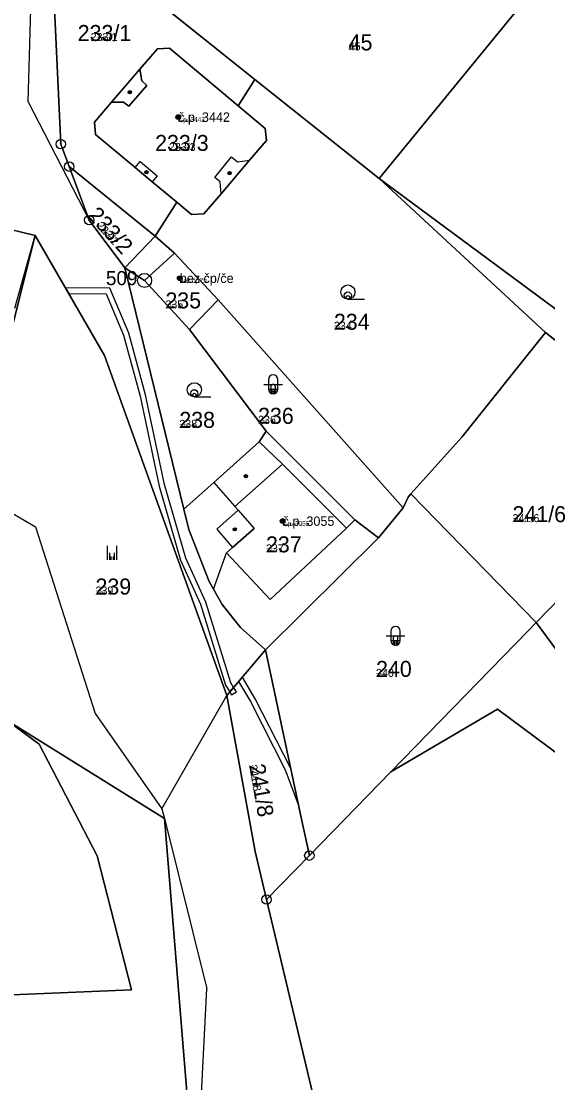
# Model space of a CAD drawing. Extents: x -759873 to -758487, y -975024 to -973516.
# Drawn here: x -759190.5 to -759134.5, y -974475 to -974362.2 of the extents above; entities that cross this region are included whole.
import ezdxf

# ---------------------------------------------------------------- set-up
doc = ezdxf.new("R2010")
doc.units = 0
for name, color, linetype in [('KAT_02_hranice parcel', 7, 'Continuous'), ('KAT_03_1000_st čísla parcelní', 7, 'Continuous'), ('KAT_03_1000_čísla parcelní', 7, 'Continuous'), ('KAT_03_1000_čísla popisná', 7, 'Continuous'), ('KAT_03_250_st čísla parcelní', 7, 'Continuous'), ('KAT_03_250_čísla parcelní', 7, 'Continuous'), ('KAT_03_250_čísla popisná', 7, 'Continuous'), ('KAT_03_500_st čísla parcelní', 7, 'Continuous'), ('KAT_03_500_čísla parcelní', 7, 'Continuous'), ('KAT_03_500_čísla popisná', 7, 'Continuous'), ('KAT_04_vnitřní kresba', 7, 'Continuous'), ('KAT_05_1000_značky kultur', 7, 'Continuous'), ('KAT_05_250_značky kultur', 7, 'Continuous'), ('KAT_05_500_značky kultur', 7, 'Continuous'), ('KAT_07_1000_značky budov', 7, 'Continuous'), ('KAT_07_250_značky budov', 7, 'Continuous'), ('KAT_07_500_značky budov', 7, 'Continuous'), ('KAT_10_věcná břemena', 7, 'Continuous'), ('KAT_11_značky bodu BP', 7, 'Continuous'), ('KAT_14_plocha_budovy', 7, 'Continuous'), ('KAT_14_plocha_pozemek', 7, 'Continuous')]:
    doc.layers.add(name, color=color, linetype=linetype)

msp = doc.modelspace()

# ---------------------------------------------------------------- linework, layer by layer
at = {"layer": 'KAT_02_hranice parcel'}
for p, q in [((-759187.42, -974350.96), (-759165.67, -974368.38)), ((-759152.45, -974378.9), (-759136.75, -974359.69)), ((-759165.67, -974368.38), (-759167.44, -974371.17)), ((-759165.67, -974368.38), (-759152.45, -974378.9)), ((-759185.4, -974377.64), (-759176.25, -974385.03)), ((-759134.79, -974395.25), (-759152.45, -974378.9)), ((-759173.96, -974381.43), (-759176.25, -974385.03)), ((-759176.25, -974385.03), (-759179.48, -974388.38)), ((-759173.22, -974414.03), (-759179.48, -974388.38)), ((-759172.63, -974394.93), (-759169.57, -974391.8)), ((-759169.57, -974391.8), (-759149.92, -974413.87)), ((-759172.63, -974394.93), (-759164.48, -974405.74)), ((-759118.43, -974408.25), (-759134.79, -974395.25)), ((-759135.77, -974426.07), (-759149.08, -974412.41)), ((-759152.54, -974417.09), (-759149.92, -974413.87)), ((-759164.53, -974428.96), (-759152.54, -974417.09)), ((-759168.64, -974433.81), (-759164.53, -974428.96)), ((-759159.88, -974450.84), (-759151.23, -974441.95)), ((-759164.42, -974455.5), (-759159.88, -974450.84)), ((-759159.14, -974477.67), (-759164.42, -974455.5))]:
    msp.add_line(p, q, dxfattribs=at)
for points in [[(-759185.4, -974377.64), (-759186.3, -974375.24), (-759187.42, -974350.96)], [(-759173.96, -974381.43), (-759176.57, -974379.26), (-759178.39, -974377.73), (-759182.6, -974374.24), (-759182.71, -974372.92), (-759180.91, -974370.79), (-759177.89, -974367.29), (-759176.03, -974365.12), (-759174.73, -974365.06), (-759167.44, -974371.17)], [(-759193.58, -974369.65), (-759193.12, -974383.97), (-759189.03, -974384.96)], [(-759167.44, -974371.17), (-759164.57, -974373.57), (-759164.44, -974374.86), (-759166.24, -974376.96), (-759169.24, -974380.53), (-759171.08, -974382.65), (-759172.42, -974382.72), (-759173.96, -974381.43)], [(-759179.48, -974388.38), (-759183.28, -974383.32), (-759185.4, -974377.64)], [(-759101.95, -974417.87), (-759125.43, -974399.29), (-759132.98, -974393.31), (-759152.45, -974378.9)], [(-759189.03, -974384.96), (-759194.73, -974407.56), (-759206.79, -974400.97), (-759217.05, -974393.25)], [(-759189.03, -974384.96), (-759181.64, -974397.69), (-759168.64, -974433.81)], [(-759176.25, -974385.03), (-759174.22, -974386.82), (-759169.57, -974391.8)], [(-759179.48, -974388.38), (-759177.4, -974389.73), (-759172.63, -974394.93)], [(-759149.08, -974412.41), (-759143.66, -974406.38), (-759134.79, -974395.25)], [(-759164.48, -974405.74), (-759165.2, -974406.88), (-759170.02, -974411.18), (-759173.22, -974414.03)], [(-759164.48, -974405.74), (-759155.04, -974415.16), (-759152.54, -974417.09)], [(-759118.43, -974408.25), (-759118.57, -974408.39), (-759133.05, -974423.28), (-759135.77, -974426.07)], [(-759149.92, -974413.87), (-759149.38, -974412.75), (-759149.08, -974412.41)], [(-759164.53, -974428.96), (-759167.2, -974426.61), (-759169.16, -974424.15), (-759170.06, -974422.53), (-759170.53, -974421.7), (-759172.69, -974416.19), (-759173.22, -974414.03)], [(-759151.23, -974441.95), (-759136.67, -974427), (-759135.77, -974426.07)], [(-759129.3, -974434.83), (-759130.77, -974432.84), (-759135.77, -974426.07)], [(-759164.53, -974428.96), (-759160.6, -974447.45), (-759159.88, -974450.84)], [(-759164.42, -974455.5), (-759165.63, -974450.4), (-759168.64, -974433.81)], [(-759151.23, -974441.95), (-759139.87, -974435.29), (-759094.03, -974469.33), (-759091.57, -974460.59)], [(-759232.25, -974467.32), (-759231.16, -974467.28), (-759178.78, -974465.1), (-759182.42, -974450.87), (-759188.61, -974438.98), (-759191.99, -974436.47)], [(-759191.99, -974436.47), (-759175.27, -974446.88), (-759172.37, -974482.45)]]:
    msp.add_lwpolyline(points, dxfattribs=at)
at = {"layer": 'KAT_03_1000_čísla popisná'}
for centre in [(-759173.82, -974372.38), (-759173.65, -974389.5), (-759162.72, -974415.3)]:
    msp.add_circle(centre, 0.25, dxfattribs=at)
at = {"layer": 'KAT_03_250_čísla popisná'}
for centre in [(-759173.82, -974372.38), (-759173.65, -974389.5), (-759162.72, -974415.3)]:
    msp.add_circle(centre, 0.0625, dxfattribs=at)
at = {"layer": 'KAT_03_500_čísla popisná'}
for centre in [(-759173.82, -974372.38), (-759173.65, -974389.5), (-759162.72, -974415.3)]:
    msp.add_circle(centre, 0.125, dxfattribs=at)
at = {"layer": 'KAT_04_vnitřní kresba'}
for p, q in [((-759189.76, -974370.74), (-759189.09, -974346.96)), ((-759177.69, -974368.53), (-759177.89, -974367.29)), ((-759179.08, -974371.21), (-759177.14, -974369.03)), ((-759177.14, -974369.03), (-759177.69, -974368.53)), ((-759189.76, -974370.74), (-759183.28, -974383.32)), ((-759180.91, -974370.79), (-759179.63, -974370.79)), ((-759179.63, -974370.79), (-759179.08, -974371.21)), ((-759178.39, -974377.73), (-759177.86, -974377.1)), ((-759177.86, -974377.1), (-759176.05, -974378.62)), ((-759169.92, -974378.78), (-759168.17, -974376.6)), ((-759168.17, -974376.6), (-759167.52, -974377.11)), ((-759167.52, -974377.11), (-759166.24, -974376.96)), ((-759176.05, -974378.62), (-759176.57, -974379.26)), ((-759169.37, -974379.27), (-759169.92, -974378.78)), ((-759169.24, -974380.53), (-759169.37, -974379.27)), ((-759191.2, -974392.69), (-759189.03, -974384.96)), ((-759177.4, -974389.73), (-759174.22, -974386.82)), ((-759165.2, -974406.88), (-759162.73, -974409.26)), ((-759167.8, -974413.73), (-759162.73, -974409.26)), ((-759162.73, -974409.26), (-759155.93, -974416.05)), ((-759198.81, -974410.16), (-759188.97, -974415.9)), ((-759170.02, -974411.18), (-759167.8, -974413.73)), ((-759169.73, -974416.14), (-759167.44, -974414.14)), ((-759167.8, -974413.73), (-759167.44, -974414.14)), ((-759167.44, -974414.14), (-759165.74, -974416.09)), ((-759155.93, -974416.05), (-759155.04, -974415.16)), ((-759188.97, -974415.9), (-759182.64, -974435.74)), ((-759169.73, -974416.14), (-759168.03, -974418.09)), ((-759168.03, -974418.09), (-759165.74, -974416.09)), ((-759164.03, -974423.64), (-759155.93, -974416.05)), ((-759170.06, -974422.53), (-759168.68, -974418.68)), ((-759168.68, -974418.68), (-759168.03, -974418.09)), ((-759168.68, -974418.68), (-759164.03, -974423.64)), ((-759175.55, -974445.87), (-759168.64, -974433.81)), ((-759182.64, -974435.74), (-759175.55, -974445.87)), ((-759175.55, -974445.87), (-759175.27, -974446.88)), ((-759175.27, -974446.88), (-759170.77, -974464.99)), ((-759171.66, -974482.19), (-759170.77, -974464.99))]:
    msp.add_line(p, q, dxfattribs=at)
at = {"layer": 'KAT_05_1000_značky kultur'}
for p, q in [((-759155.78, -974391.71), (-759154.03, -974391.71)), ((-759164.73, -974400.77), (-759162.73, -974400.77)), ((-759164.23, -974400.27), (-759164.23, -974401.27)), ((-759163.23, -974401.27), (-759163.23, -974400.27)), ((-759172.1, -974402.09), (-759170.35, -974402.09)), ((-759181.33, -974419.42), (-759181.33, -974417.92)), ((-759180.33, -974419.42), (-759180.33, -974417.92)), ((-759151.72, -974427.49), (-759149.72, -974427.49)), ((-759151.22, -974426.99), (-759151.22, -974427.99)), ((-759150.22, -974427.99), (-759150.22, -974426.99))]:
    msp.add_line(p, q, dxfattribs=at)
for centre in [(-759155.78, -974390.96), (-759172.1, -974401.34)]:
    msp.add_circle(centre, 0.75, dxfattribs=at)
for centre, start, end in [((-759163.73, -974400.27), 0, 180), ((-759163.73, -974401.27), 180, 359.9879), ((-759150.72, -974426.99), 0, 180), ((-759150.72, -974427.99), 180, 359.9879)]:
    msp.add_arc(centre, 0.5, start, end, dxfattribs=at)
at = {"layer": 'KAT_05_250_značky kultur'}
for p, q in [((-759155.79, -974391.71), (-759155.35, -974391.71)), ((-759172.11, -974402.09), (-759171.67, -974402.09)), ((-759163.98, -974401.52), (-759163.48, -974401.52)), ((-759163.86, -974401.4), (-759163.86, -974401.65)), ((-759163.6, -974401.65), (-759163.6, -974401.4)), ((-759180.95, -974419.42), (-759180.95, -974419.05)), ((-759180.7, -974419.42), (-759180.7, -974419.05)), ((-759150.97, -974428.24), (-759150.47, -974428.24)), ((-759150.85, -974428.12), (-759150.85, -974428.37)), ((-759150.59, -974428.37), (-759150.59, -974428.12))]:
    msp.add_line(p, q, dxfattribs=at)
for centre in [(-759155.79, -974391.52), (-759172.11, -974401.9)]:
    msp.add_circle(centre, 0.187, dxfattribs=at)
for centre, start, end in [((-759163.73, -974401.4), 0, 180), ((-759163.73, -974401.65), 180, 359.9879), ((-759150.72, -974428.12), 0, 180), ((-759150.72, -974428.37), 180, 359.9879)]:
    msp.add_arc(centre, 0.125, start, end, dxfattribs=at)
at = {"layer": 'KAT_05_500_značky kultur'}
for p, q in [((-759155.79, -974391.71), (-759154.91, -974391.71)), ((-759172.11, -974402.09), (-759171.23, -974402.09)), ((-759164.23, -974401.27), (-759163.23, -974401.27)), ((-759163.98, -974401.02), (-759163.98, -974401.52)), ((-759163.48, -974401.52), (-759163.48, -974401.02)), ((-759181.08, -974419.42), (-759181.08, -974418.67)), ((-759180.58, -974419.42), (-759180.58, -974418.67)), ((-759151.22, -974427.99), (-759150.22, -974427.99)), ((-759150.97, -974427.74), (-759150.97, -974428.24)), ((-759150.47, -974428.24), (-759150.47, -974427.74))]:
    msp.add_line(p, q, dxfattribs=at)
for centre in [(-759155.79, -974391.33), (-759172.11, -974401.71)]:
    msp.add_circle(centre, 0.375, dxfattribs=at)
for centre, start, end in [((-759163.73, -974401.02), 0, 180), ((-759163.73, -974401.52), 180, 359.9879), ((-759150.72, -974427.74), 0, 180), ((-759150.72, -974428.24), 180, 359.9879)]:
    msp.add_arc(centre, 0.25, start, end, dxfattribs=at)
at = {"layer": 'KAT_07_1000_značky budov'}
for centre in [(-759178.97, -974369.73), (-759173.83, -974372.38), (-759177.19, -974378.23), (-759168.36, -974378.33), (-759173.66, -974389.5), (-759166.62, -974410.53), (-759162.73, -974415.3), (-759167.8, -974416.17)]:
    msp.add_circle(centre, 0.175, dxfattribs=at)
at = {"layer": 'KAT_07_250_značky budov'}
for centre in [(-759178.96, -974369.73), (-759173.82, -974372.38), (-759177.18, -974378.23), (-759168.35, -974378.33), (-759173.65, -974389.5), (-759166.61, -974410.53), (-759162.72, -974415.3), (-759167.79, -974416.17)]:
    msp.add_circle(centre, 0.0437, dxfattribs=at)
at = {"layer": 'KAT_07_500_značky budov'}
for centre in [(-759178.96, -974369.73), (-759173.82, -974372.38), (-759177.18, -974378.23), (-759168.35, -974378.33), (-759173.65, -974389.5), (-759166.61, -974410.53), (-759162.72, -974415.3), (-759167.79, -974416.17)]:
    msp.add_circle(centre, 0.0875, dxfattribs=at)
at = {"layer": 'KAT_10_věcná břemena'}
for points in [[(-759168.33, -974433.45), (-759167.93, -974432.97), (-759168.24, -974432.47), (-759170.89, -974423.9), (-759173.01, -974419.24), (-759175.27, -974411.42), (-759177.29, -974401.89), (-759179.05, -974395.34), (-759181.09, -974390.56), (-759185.81, -974390.51), (-759185.46, -974391.11), (-759181.49, -974391.16), (-759179.62, -974395.54), (-759177.87, -974402.03), (-759175.85, -974411.57), (-759173.58, -974419.45), (-759171.46, -974424.11), (-759168.79, -974432.72)], [(-759166.15, -974434.47), (-759162.44, -974441.72), (-759160.99, -974445.6), (-759161.85, -974441.59), (-759165.63, -974434.19), (-759167, -974431.87), (-759167.41, -974432.35)], [(-759167.93, -974432.97), (-759168.33, -974433.45), (-759168.14, -974433.75), (-759167.63, -974433.43)]]:
    msp.add_lwpolyline(points, close=True, dxfattribs=at)
at = {"layer": 'KAT_11_značky bodu BP'}
for centre, radius in [((-759186.3, -974375.24), 0.5), ((-759186.3, -974375.24), 0.0303), ((-759185.4, -974377.64), 0.5), ((-759185.4, -974377.64), 0.0303), ((-759183.28, -974383.32), 0.5), ((-759183.28, -974383.32), 0.0303), ((-759177.4, -974389.73), 0.75), ((-759177.4, -974389.73), 0.03), ((-759159.88, -974450.84), 0.5), ((-759159.88, -974450.84), 0.0303), ((-759164.42, -974455.5), 0.5), ((-759164.42, -974455.5), 0.0303)]:
    msp.add_circle(centre, radius, dxfattribs=at)
at = {"layer": 'KAT_14_plocha_budovy'}
for points in [[(-759177.86, -974377.1), (-759176.05, -974378.62), (-759176.57, -974379.26), (-759173.96, -974381.43), (-759172.42, -974382.72), (-759171.08, -974382.65), (-759169.24, -974380.53), (-759169.37, -974379.27), (-759169.92, -974378.78), (-759168.17, -974376.6), (-759167.52, -974377.11), (-759166.24, -974376.96), (-759164.44, -974374.86), (-759164.57, -974373.57), (-759167.44, -974371.17), (-759174.73, -974365.06), (-759176.03, -974365.12), (-759177.89, -974367.29), (-759177.69, -974368.53), (-759177.14, -974369.03), (-759179.08, -974371.21), (-759179.63, -974370.79), (-759180.91, -974370.79), (-759182.71, -974372.92), (-759182.6, -974374.24), (-759178.39, -974377.73)], [(-759177.4, -974389.73), (-759172.63, -974394.93), (-759169.57, -974391.8), (-759174.22, -974386.82)], [(-759168.68, -974418.68), (-759164.03, -974423.64), (-759155.93, -974416.05), (-759162.73, -974409.26), (-759167.8, -974413.73), (-759167.44, -974414.14), (-759165.74, -974416.09), (-759168.03, -974418.09)]]:
    msp.add_lwpolyline(points, close=True, dxfattribs=at)
at = {"layer": 'KAT_14_plocha_pozemek'}
for points in [[(-759136.75, -974359.69), (-759150.34, -974345.43), (-759158.52, -974352.8), (-759166, -974360.47), (-759185.19, -974336.95), (-759187.42, -974350.96), (-759165.67, -974368.38), (-759152.45, -974378.9)], [(-759090.51, -974368.61), (-759115.29, -974346.47), (-759121.28, -974341.12), (-759136.75, -974359.69), (-759152.45, -974378.9), (-759132.98, -974393.31), (-759125.43, -974399.29), (-759101.95, -974417.87), (-759100.34, -974415.37), (-759089.09, -974397.95), (-759086.82, -974394.42), (-759097.98, -974384.46), (-759087.85, -974371.54), (-759087.6, -974371.21)], [(-759180.91, -974370.79), (-759177.89, -974367.29), (-759176.03, -974365.12), (-759174.73, -974365.06), (-759167.44, -974371.17), (-759165.67, -974368.38), (-759187.42, -974350.96), (-759186.3, -974375.24), (-759185.4, -974377.64), (-759176.25, -974385.03), (-759173.96, -974381.43), (-759176.57, -974379.26), (-759178.39, -974377.73), (-759182.6, -974374.24), (-759182.71, -974372.92)], [(-759167.44, -974371.17), (-759174.73, -974365.06), (-759176.03, -974365.12), (-759177.89, -974367.29), (-759180.91, -974370.79), (-759182.71, -974372.92), (-759182.6, -974374.24), (-759178.39, -974377.73), (-759176.57, -974379.26), (-759173.96, -974381.43), (-759172.42, -974382.72), (-759171.08, -974382.65), (-759169.24, -974380.53), (-759166.24, -974376.96), (-759164.44, -974374.86), (-759164.57, -974373.57)], [(-759193.58, -974369.65), (-759197.19, -974369.51), (-759206.27, -974369.15), (-759206.8, -974379.96), (-759211.91, -974379.77), (-759213.72, -974379.28), (-759217.05, -974393.25), (-759206.79, -974400.97), (-759194.73, -974407.56), (-759189.03, -974384.96), (-759193.12, -974383.97)], [(-759166.24, -974376.96), (-759169.24, -974380.53), (-759171.08, -974382.65), (-759172.42, -974382.72), (-759173.96, -974381.43), (-759176.25, -974385.03), (-759174.22, -974386.82), (-759169.57, -974391.8), (-759149.92, -974413.87), (-759149.38, -974412.75), (-759149.08, -974412.41), (-759143.66, -974406.38), (-759134.79, -974395.25), (-759152.45, -974378.9), (-759165.67, -974368.38), (-759167.44, -974371.17), (-759164.57, -974373.57), (-759164.44, -974374.86)], [(-759179.48, -974388.38), (-759176.25, -974385.03), (-759185.4, -974377.64), (-759183.28, -974383.32)], [(-759101.95, -974417.87), (-759125.43, -974399.29), (-759132.98, -974393.31), (-759152.45, -974378.9), (-759134.79, -974395.25), (-759118.43, -974408.25), (-759110.46, -974414.59), (-759103.4, -974420.2)], [(-759175.27, -974446.88), (-759172.37, -974482.45), (-759171.66, -974482.19), (-759159.14, -974477.67), (-759164.42, -974455.5), (-759165.63, -974450.4), (-759168.64, -974433.81), (-759181.64, -974397.69), (-759189.03, -974384.96), (-759194.73, -974407.56), (-759206.79, -974400.97), (-759217.05, -974393.25), (-759219.59, -974401.14), (-759220.81, -974404.94), (-759225.77, -974404.63), (-759227.77, -974404.51), (-759229.03, -974406.06), (-759225.39, -974407.7), (-759207.13, -974415.97), (-759198.3, -974417.97), (-759197.39, -974426.02), (-759191.99, -974436.47)], [(-759176.25, -974385.03), (-759179.48, -974388.38), (-759177.4, -974389.73), (-759172.63, -974394.93), (-759169.57, -974391.8), (-759174.22, -974386.82)], [(-759179.48, -974388.38), (-759173.22, -974414.03), (-759170.02, -974411.18), (-759165.2, -974406.88), (-759164.48, -974405.74), (-759172.63, -974394.93), (-759177.4, -974389.73)], [(-759149.92, -974413.87), (-759169.57, -974391.8), (-759172.63, -974394.93), (-759164.48, -974405.74), (-759155.04, -974415.16), (-759152.54, -974417.09)], [(-759118.43, -974408.25), (-759134.79, -974395.25), (-759143.66, -974406.38), (-759149.08, -974412.41), (-759135.77, -974426.07), (-759133.05, -974423.28), (-759118.57, -974408.39)], [(-759152.54, -974417.09), (-759155.04, -974415.16), (-759164.48, -974405.74), (-759165.2, -974406.88), (-759170.02, -974411.18), (-759173.22, -974414.03), (-759172.69, -974416.19), (-759170.53, -974421.7), (-759170.06, -974422.53), (-759169.16, -974424.15), (-759167.2, -974426.61), (-759164.53, -974428.96)], [(-759118.57, -974408.39), (-759133.05, -974423.28), (-759135.77, -974426.07), (-759130.77, -974432.84), (-759129.3, -974434.83), (-759129.04, -974434.55), (-759127.21, -974432.58), (-759110.61, -974414.75), (-759110.46, -974414.59), (-759118.43, -974408.25)], [(-759135.77, -974426.07), (-759149.08, -974412.41), (-759149.38, -974412.75), (-759149.92, -974413.87), (-759152.54, -974417.09), (-759164.53, -974428.96), (-759160.6, -974447.45), (-759159.88, -974450.84), (-759151.23, -974441.95), (-759136.67, -974427)], [(-759188.61, -974438.98), (-759191.99, -974436.47), (-759197.39, -974426.02), (-759200.15, -974427.87), (-759201.28, -974430.17), (-759214.69, -974444.47), (-759232.25, -974467.32), (-759231.16, -974467.28), (-759178.78, -974465.1), (-759182.42, -974450.87)], [(-759120.38, -974442.39), (-759121.83, -974441.16), (-759125.6, -974437.96), (-759129.3, -974434.83), (-759130.77, -974432.84), (-759135.77, -974426.07), (-759136.67, -974427), (-759151.23, -974441.95), (-759139.87, -974435.29), (-759094.03, -974469.33), (-759091.57, -974460.59), (-759105.53, -974451.97)], [(-759159.88, -974450.84), (-759160.6, -974447.45), (-759164.53, -974428.96), (-759168.64, -974433.81), (-759165.63, -974450.4), (-759164.42, -974455.5)]]:
    msp.add_lwpolyline(points, close=True, dxfattribs=at)
for points in [[(-759193.12, -974383.97), (-759189.03, -974384.96), (-759181.64, -974397.69), (-759168.64, -974433.81), (-759164.53, -974428.96), (-759167.2, -974426.61), (-759169.16, -974424.15), (-759170.06, -974422.53), (-759170.53, -974421.7), (-759172.69, -974416.19), (-759173.22, -974414.03), (-759179.48, -974388.38), (-759183.28, -974383.32), (-759185.4, -974377.64), (-759186.3, -974375.24), (-759187.42, -974350.96)], [(-759058.24, -974378.96), (-759093.33, -974426.86), (-759081.81, -974435.94), (-759082.1, -974437), (-759088.9, -974462.24), (-759091.57, -974460.59), (-759094.03, -974469.33), (-759139.87, -974435.29), (-759151.23, -974441.95), (-759159.88, -974450.84), (-759164.42, -974455.5), (-759159.14, -974477.67)], [(-759172.37, -974482.45), (-759175.27, -974446.88), (-759191.99, -974436.47), (-759188.61, -974438.98), (-759182.42, -974450.87), (-759178.78, -974465.1), (-759231.16, -974467.28), (-759232.25, -974467.32), (-759227.79, -974493.47)]]:
    msp.add_lwpolyline(points, dxfattribs=at)

# ---------------------------------------------------------------- texts
at = {"layer": 'KAT_03_1000_st čísla parcelní'}
for s, p in [('233/3', (-759176.27, -974375.97)), ('235', (-759175.18, -974392.7)), ('237', (-759164.49, -974418.62))]:
    msp.add_text(s, height=1.7, dxfattribs=at).set_placement(p)
at = {"layer": 'KAT_03_1000_čísla parcelní'}
for s, p in [('233/1', (-759184.5, -974364.29)), ('45', (-759155.7, -974365.29)), ('234', (-759157.27, -974394.97)), ('236', (-759165.33, -974404.96)), ('238', (-759173.7, -974405.39)), ('241/6', (-759138.28, -974415.41)), ('239', (-759182.61, -974423.1)), ('240', (-759152.79, -974431.85))]:
    msp.add_text(s, height=1.7, dxfattribs=at).set_placement(p)
for s, rotation, p in [('233/2', 312, (-759183.56, -974382.86)), ('241/8', 280, (-759166.29, -974441.24))]:
    msp.add_text(s, height=1.7, rotation=rotation, dxfattribs=at).set_placement(p)
at = {"layer": 'KAT_03_1000_čísla popisná'}
for s, p in [('č.p. 3442', (-759173.82, -974372.88)), ('bez čp/če', (-759173.65, -974390)), ('č.p. 3055', (-759162.72, -974415.8))]:
    msp.add_text(s, height=1, dxfattribs=at).set_placement(p)
at = {"layer": 'KAT_03_250_st čísla parcelní'}
for s, p in [('233/3', (-759174.09, -974375.97)), ('235', (-759175.18, -974392.7)), ('237', (-759164.49, -974418.62))]:
    msp.add_text(s, height=0.425, dxfattribs=at).set_placement(p)
at = {"layer": 'KAT_03_250_čísla parcelní'}
for s, p in [('233/1', (-759182.44, -974364.29)), ('45', (-759155.7, -974365.29)), ('234', (-759157.27, -974394.97)), ('238', (-759173.7, -974405.39)), ('236', (-759165.33, -974404.96)), ('241/6', (-759138.28, -974415.41)), ('239', (-759182.61, -974423.1)), ('240', (-759152.79, -974431.85))]:
    msp.add_text(s, height=0.425, dxfattribs=at).set_placement(p)
for s, rotation, p in [('233/2', 312, (-759182.1, -974384.48)), ('241/8', 280, (-759166.29, -974441.24))]:
    msp.add_text(s, height=0.425, rotation=rotation, dxfattribs=at).set_placement(p)
at = {"layer": 'KAT_03_250_čísla popisná'}
for s, p in [('č.p. 3442', (-759173.82, -974372.88)), ('bez čp/če', (-759173.65, -974390)), ('č.p. 3055', (-759162.72, -974415.8))]:
    msp.add_text(s, height=0.25, dxfattribs=at).set_placement(p)
at = {"layer": 'KAT_03_500_st čísla parcelní'}
for s, p in [('233/3', (-759174.81, -974375.97)), ('235', (-759175.18, -974392.7)), ('237', (-759164.49, -974418.62))]:
    msp.add_text(s, height=0.85, dxfattribs=at).set_placement(p)
at = {"layer": 'KAT_03_500_čísla parcelní'}
for s, p in [('233/1', (-759183.13, -974364.29)), ('45', (-759155.7, -974365.29)), ('234', (-759157.27, -974394.97)), ('236', (-759165.33, -974404.96)), ('238', (-759173.7, -974405.39)), ('241/6', (-759138.28, -974415.41)), ('239', (-759182.61, -974423.1)), ('240', (-759152.79, -974431.85))]:
    msp.add_text(s, height=0.85, dxfattribs=at).set_placement(p)
for s, rotation, p in [('233/2', 312, (-759182.58, -974383.94)), ('241/8', 280, (-759166.29, -974441.24))]:
    msp.add_text(s, height=0.85, rotation=rotation, dxfattribs=at).set_placement(p)
at = {"layer": 'KAT_03_500_čísla popisná'}
for s, p in [('č.p. 3442', (-759173.82, -974372.88)), ('bez čp/če', (-759173.65, -974390)), ('č.p. 3055', (-759162.72, -974415.8))]:
    msp.add_text(s, height=0.5, dxfattribs=at).set_placement(p)
at = {"layer": 'KAT_11_značky bodu BP'}
msp.add_text('509', height=1.5, dxfattribs=at).set_placement((-759181.5, -974390.23))

doc.saveas('drawing.dxf')
